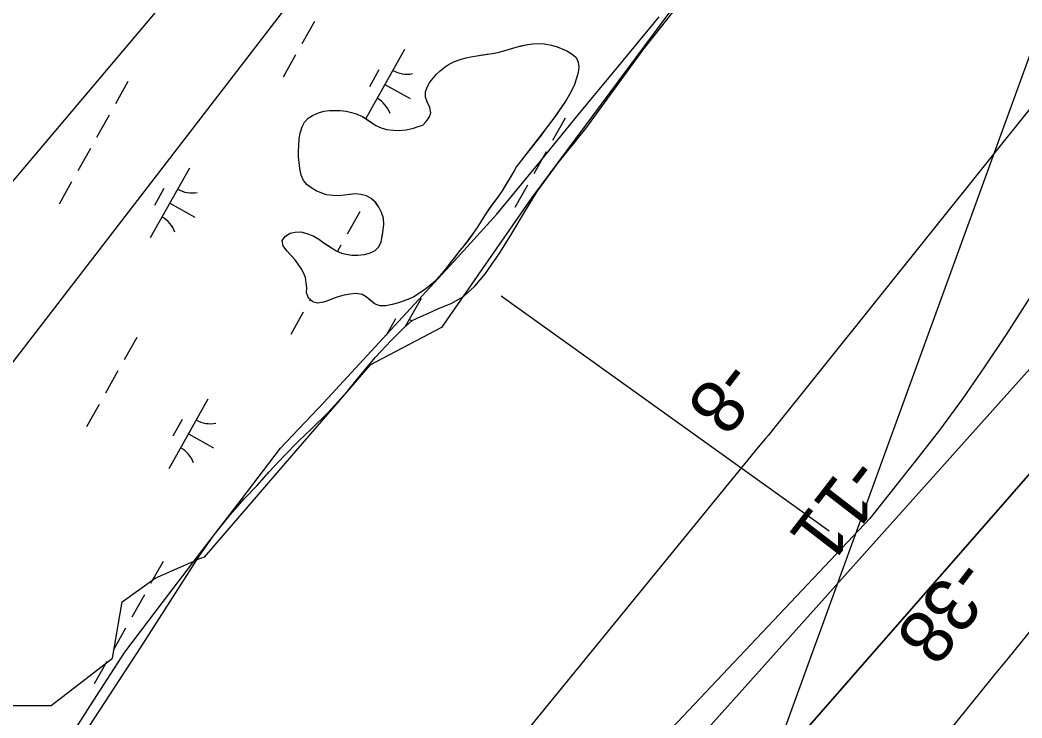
# Model space of a CAD drawing. Extents: x 3913936 to 3933962, y 195330 to 217741.
# Drawn here: x 3922323 to 3922950, y 202121 to 202558 of the extents above; entities that cross this region are included whole.
import ezdxf

# ---------------------------------------------------------------- set-up
doc = ezdxf.new("R2010")
doc.units = 0
for name, color, linetype in [('V-ANNO-TEXT', 7, 'Continuous'), ('V-LEVE-TOET', 7, 'Continuous'), ('V-RIVR-EDGE', 7, 'Continuous'), ('V-RIVR-RANG', 7, 'Continuous'), ('V-RRAP-FSHR', 7, 'Continuous'), ('V-TOPO-DPTH', 7, 'Continuous'), ('V-TOPO-MINR', 7, 'Continuous'), ('V-TOPO-SHOR', 7, 'Continuous'), ('V-UTIL-LINE', 7, 'Continuous'), ('V-WETL-SWMP', 7, 'Continuous')]:
    doc.layers.add(name, color=color, linetype=linetype)

msp = doc.modelspace()

# ---------------------------------------------------------------- linework, layer by layer
at = {"layer": 'V-ANNO-TEXT'}
msp.add_lwpolyline([(3923713.15, 204620.63), (3922595.25, 201547.11)], dxfattribs=at)
at = {"layer": 'V-LEVE-TOET'}
msp.add_line((3922624.2, 202385.16), (3922829.43, 202238.05), dxfattribs=at)
at = {"layer": 'V-RIVR-EDGE'}
for points in [[(3923006.45, 202985.36), (3922949.87, 202946.46), (3922920.41, 202907.57), (3922890.94, 202843.92), (3922886.22, 202788.52), (3922866.19, 202747.26), (3922643.41, 202446.69), (3922586.83, 202365.36), (3922542.04, 202341.78), (3922489, 202280.49), (3922438.31, 202221.56), (3922433.64, 202219.89)], [(3922301.36, 202128.83), (3922342.66, 202128.83), (3922381.02, 202158.33), (3922386.92, 202193.73), (3922407.57, 202208.48), (3922433.64, 202219.89)]]:
    msp.add_lwpolyline(points, dxfattribs=at)
at = {"layer": 'V-RRAP-FSHR'}
msp.add_lwpolyline([(3922302.51, 202027.32), (3922324.2, 202061.57), (3922345.5, 202094.79), (3922366.99, 202128.52), (3922388.58, 202162.2), (3922412.85, 202193.98), (3922437.13, 202225.77), (3922461.41, 202257.56), (3922486.14, 202289.78), (3922513.12, 202318.49), (3922540.22, 202347.91), (3922567.33, 202377.33), (3922594.43, 202406.74), (3922621.49, 202436.2), (3922646.86, 202467.13), (3922672.22, 202498.55), (3922697.59, 202528.98), (3922722.95, 202559.91)], dxfattribs=at)
at = {"layer": 'V-TOPO-DPTH'}
for points in [[(3923377.96, 202699), (3922941.35, 202158.48), (3922940.31, 202157.2), (3922937.13, 202153.43), (3922933.95, 202149.66), (3922932.91, 202148.38), (3922620.43, 201761.19), (3922567.77, 201695.94), (3922515.1, 201630.7), (3922462.43, 201565.47), (3922409.75, 201500.24), (3922320.06, 201389.21), (3922312.18, 201379.53), (3922304.23, 201369.9), (3922296.21, 201360.34), (3922288.13, 201350.82), (3922167.81, 201210.31), (3922100.01, 201130.19), (3922032.83, 201049.55), (3921966.59, 200968.13), (3921900.98, 200886.2)], [(3923377.96, 202699), (3922941.35, 202158.48), (3922940.31, 202157.2), (3922937.13, 202153.43), (3922933.95, 202149.66), (3922932.91, 202148.38), (3922620.43, 201761.19), (3922567.77, 201695.94), (3922515.1, 201630.7), (3922462.43, 201565.47), (3922409.75, 201500.24), (3922320.06, 201389.21), (3922312.18, 201379.53), (3922304.23, 201369.9), (3922296.21, 201360.34), (3922288.13, 201350.82), (3922167.81, 201210.31), (3922100.01, 201130.19), (3922032.83, 201049.55), (3921966.59, 200968.13), (3921900.98, 200886.2)], [(3923095.91, 202678.46), (3922791.11, 202297.8), (3922789.59, 202295.95), (3922787.26, 202293.23), (3922784.95, 202290.48), (3922157.44, 201521.67), (3922155.7, 201519.54), (3922153.96, 201517.41), (3922152.21, 201515.29), (3922150.47, 201513.16), (3922148.07, 201510.25), (3922146.97, 201508.92), (3922146.42, 201508.26), (3922145.87, 201507.61), (3922141.95, 201502.95), (3922139.44, 201499.96), (3922136.94, 201496.96), (3922134.44, 201493.96), (3922131.96, 201490.95), (3921528.01, 200758.19)], [(3923045.56, 202377.72), (3922233.85, 201449.62), (3922231.73, 201447.13), (3922229.61, 201444.64), (3922227.46, 201442.17), (3922225.3, 201439.71), (3922161.81, 201367.9), (3922127.91, 201329.54), (3922094.02, 201291.17), (3922060.15, 201252.77), (3922026.29, 201214.37), (3921757.53, 200909.33)], [(3921757.53, 200909.33), (3922026.29, 201214.37), (3922060.15, 201252.77), (3922094.02, 201291.17), (3922127.91, 201329.54), (3922161.81, 201367.9), (3922225.3, 201439.71), (3922227.46, 201442.17), (3922229.61, 201444.64), (3922231.73, 201447.13), (3922233.85, 201449.62), (3923045.56, 202377.72)], [(3921571.56, 200731.02), (3921771, 200981.89), (3921838.64, 201066.04), (3921906.88, 201149.7), (3921976, 201232.63), (3922045.72, 201315.07), (3922153.04, 201440.58), (3922169.51, 201459.92), (3922185.93, 201479.31), (3922202.27, 201498.77), (3922970.95, 202357.51)], [(3921571.56, 200731.02), (3921771, 200981.89), (3921838.64, 201066.04), (3921906.88, 201149.7), (3921976, 201232.63), (3922045.72, 201315.07), (3922153.04, 201440.58), (3922169.51, 201459.92), (3922185.93, 201479.31), (3922202.27, 201498.77), (3922970.95, 202357.51)]]:
    msp.add_lwpolyline(points, dxfattribs=at)
at = {"layer": 'V-TOPO-MINR'}
for points in [[(3923377.96, 202699), (3922941.35, 202158.48), (3922940.31, 202157.2), (3922937.13, 202153.43), (3922933.95, 202149.66), (3922932.91, 202148.38), (3922620.43, 201761.19), (3922567.77, 201695.94), (3922515.1, 201630.7), (3922462.43, 201565.47), (3922409.75, 201500.24), (3922320.06, 201389.21), (3922312.18, 201379.53), (3922304.23, 201369.9), (3922296.21, 201360.34), (3922288.13, 201350.82), (3922167.81, 201210.31), (3922100.01, 201130.19), (3922032.83, 201049.55), (3921966.59, 200968.13), (3921900.98, 200886.2)], [(3923095.91, 202678.46), (3922791.11, 202297.8), (3922789.59, 202295.95), (3922787.26, 202293.23), (3922784.95, 202290.48), (3922157.44, 201521.67), (3922155.7, 201519.54), (3922153.96, 201517.41), (3922152.21, 201515.29), (3922150.47, 201513.16), (3922148.07, 201510.25), (3922146.97, 201508.92), (3922146.42, 201508.26), (3922145.87, 201507.61), (3922141.95, 201502.95), (3922139.44, 201499.96), (3922136.94, 201496.96), (3922134.44, 201493.96), (3922131.96, 201490.95), (3921528.01, 200758.19)], [(3922956.69, 202387.01), (3922940, 202360.98), (3922926.57, 202340.72), (3922912.73, 202320.75), (3922898.3, 202301.2), (3922883.47, 202281.95), (3922854.79, 202245.85), (3922330.9, 201690.94), (3922303.28, 201658.32), (3922275.74, 201625.63), (3922248.33, 201592.82), (3922221.02, 201559.94), (3922183.26, 201514.3), (3922174.87, 201504.2), (3922166.46, 201494.11), (3922158, 201484.06), (3922149.52, 201474.03), (3922091.91, 201406.13), (3922054.74, 201362.05), (3922017.74, 201317.82), (3921981.01, 201273.38), (3921944.45, 201228.79), (3921549.88, 200744.53)], [(3923045.56, 202377.72), (3922233.85, 201449.62), (3922231.73, 201447.13), (3922229.61, 201444.64), (3922227.46, 201442.17), (3922225.3, 201439.71), (3922161.81, 201367.9), (3922127.91, 201329.54), (3922094.02, 201291.17), (3922060.15, 201252.77), (3922026.29, 201214.37), (3921757.53, 200909.33)], [(3922970.95, 202357.51), (3922202.27, 201498.77), (3922185.93, 201479.31), (3922169.51, 201459.92), (3922153.04, 201440.58), (3922045.72, 201315.07), (3921976, 201232.63), (3921906.88, 201149.7), (3921838.64, 201066.04), (3921771, 200981.89), (3921571.56, 200731.02)]]:
    msp.add_lwpolyline(points, dxfattribs=at)
at = {"layer": 'V-TOPO-SHOR'}
for points in [[(3922502.82, 202454.65), (3922500.49, 202457.39), (3922499.1, 202460.75), (3922498.23, 202464.79), (3922497.7, 202468.66), (3922497.43, 202472.27), (3922497.34, 202475.63), (3922497.5, 202479.16), (3922497.83, 202483.38), (3922498.34, 202486.9), (3922499.53, 202490.86), (3922501.16, 202493.97), (3922503.48, 202496.47), (3922506.14, 202498.11), (3922509.75, 202499.76), (3922513.19, 202500.8), (3922516.71, 202501.24), (3922519.73, 202501.16), (3922523.34, 202501.09), (3922527.21, 202500.67), (3922530.4, 202499.99), (3922533.41, 202499.05), (3922537.38, 202497.42), (3922540.22, 202495.54), (3922543.07, 202493.65), (3922545.82, 202491.85), (3922549.01, 202490.23), (3922552.46, 202489.29), (3922556.76, 202488.87), (3922560.38, 202488.71), (3922564.68, 202489.15), (3922569.23, 202490.03), (3922572.25, 202491.15), (3922575.17, 202492.02), (3922577.31, 202494.27), (3922579.03, 202496.77), (3922580.22, 202499.78), (3922579.44, 202503.14), (3922577.88, 202506.57), (3922576.84, 202509.49), (3922576.83, 202512.85), (3922577.94, 202515.87), (3922579.57, 202518.88), (3922581.62, 202521.38), (3922583.77, 202523.88), (3922586, 202526.04), (3922589, 202528.46), (3922591.5, 202530.27), (3922595.02, 202531.83), (3922599.15, 202533.22), (3922602.16, 202534.09), (3922605.16, 202534.79), (3922608.95, 202535.48), (3922612.39, 202536.01), (3922615.4, 202536.36), (3922618.5, 202536.8), (3922622.11, 202537.5), (3922625.89, 202538.54), (3922629.33, 202539.5), (3922633.54, 202540.89), (3922637.5, 202541.85), (3922640.6, 202542.54), (3922643.87, 202542.98), (3922647.22, 202543.16), (3922651.27, 202542.92), (3922655.57, 202542.15), (3922659.19, 202540.96), (3922662.29, 202539.68), (3922665.13, 202538.48), (3922668.58, 202536.34), (3922670.99, 202534.28), (3922672.29, 202531.45), (3922672.73, 202528.35), (3922672.31, 202524.99), (3922671.37, 202521.46), (3922669.92, 202517.5), (3922668.47, 202514.31), (3922666.93, 202511.3), (3922665.22, 202508.36), (3922663.25, 202505.26), (3922660.93, 202501.73), (3922658.96, 202498.88), (3922656.56, 202495.52), (3922653.82, 202491.9), (3922651.33, 202488.62), (3922649.36, 202486.03), (3922636.07, 202468.96)], [(3922636.07, 202468.96), (3922633.75, 202466.03), (3922632.3, 202463.36), (3922630.5, 202460.43), (3922628.79, 202457.49), (3922626.3, 202453.44), (3922624.67, 202450.86), (3922622.79, 202448.1), (3922620.73, 202445.34), (3922618.68, 202442.58), (3922616.7, 202439.82), (3922614.73, 202436.98), (3922613.02, 202434.22), (3922611.13, 202431.37), (3922609.08, 202428.01), (3922606.68, 202424.39), (3922603.85, 202420.51), (3922600.85, 202416.54), (3922598.36, 202413.61), (3922594.93, 202409.12), (3922592.27, 202405.85), (3922589.7, 202402.49), (3922587.21, 202399.38), (3922584.9, 202396.79), (3922582.84, 202394.46), (3922579.06, 202391.18), (3922576.23, 202389.02), (3922573.57, 202387.3), (3922569.53, 202384.62), (3922566.69, 202383.32), (3922562.91, 202381.93), (3922559.81, 202380.89), (3922555.95, 202379.67), (3922551.99, 202378.89), (3922548.38, 202378.96), (3922545.36, 202379.9), (3922542.6, 202382.13), (3922539.75, 202384.53), (3922537.08, 202385.99), (3922533.21, 202386.67), (3922529.68, 202386.31), (3922525.98, 202385.61), (3922522.8, 202384.74), (3922519.71, 202383.7), (3922516.01, 202382.23), (3922512.92, 202381.19), (3922509.31, 202380.66), (3922506.21, 202381.51), (3922503.62, 202383.66), (3922502.32, 202387.27), (3922502.48, 202390.28), (3922502.21, 202393.29), (3922501.77, 202396.56), (3922500.56, 202399.57), (3922499, 202402.23), (3922497.19, 202404.98), (3922494.95, 202407.99), (3922492.18, 202410.99), (3922489.94, 202413.31), (3922487.69, 202416.49), (3922487.17, 202419.75), (3922489.23, 202422.51), (3922492.15, 202424.33), (3922495.33, 202425.11), (3922498.85, 202425.21), (3922502.47, 202424.27), (3922506.95, 202422.48), (3922510.14, 202420.68), (3922512.56, 202418.79), (3922515.23, 202416.99), (3922518.33, 202415.02), (3922521, 202413.4), (3922524.19, 202411.94), (3922527.12, 202411.18), (3922530.65, 202410.67), (3922534.43, 202410.68), (3922538.65, 202410.95), (3922542.43, 202412.08), (3922545.27, 202413.63), (3922547.58, 202415.79), (3922549.04, 202418.98), (3922549.89, 202423.46), (3922550.39, 202426.55), (3922550.73, 202429.83), (3922550.55, 202433.87), (3922549.25, 202437.39), (3922547.52, 202440.66), (3922545.61, 202443.58), (3922542.85, 202446.07), (3922539.92, 202447.7), (3922536.31, 202448.63), (3922533.3, 202448.97), (3922529.25, 202448.53), (3922526.07, 202448.09), (3922522.89, 202447.82), (3922518.75, 202447.89), (3922514.88, 202448.31), (3922511.87, 202449.34), (3922508.42, 202450.96), (3922505.58, 202452.59), (3922502.82, 202454.65)]]:
    msp.add_lwpolyline(points, dxfattribs=at)
at = {"layer": 'V-UTIL-LINE'}
for points in [[(3928315.82, 212388.13), (3926944.7, 210748.94), (3926592.74, 210251.47), (3926408.93, 209914.99), (3925628.64, 208474.44), (3925139.98, 207727.42), (3924555.96, 206253.65), (3924055.82, 204771.45), (3923484.9, 203858.52), (3922256.01, 202262.65), (3921816.4, 201905.57), (3920704.84, 200345.08), (3920462.44, 200062.72)], [(3928328.32, 212380.93), (3926784.14, 210502.92), (3926424.72, 209908.68), (3925640.45, 208467.64), (3924952.2, 207329.25), (3923971.74, 204752.16), (3923252.9, 203563.68), (3921560.17, 201558.84), (3920397.87, 200112.86)]]:
    msp.add_lwpolyline(points, dxfattribs=at)
at = {"layer": 'V-WETL-SWMP'}
for p, q in [((3922712.83, 202538.87), (3922754.11, 202591.47)), ((3922507.32, 202556.9), (3922499.48, 202542.95)), ((3922633.54, 202540.89), (3922640.6, 202542.54)), ((3922640.6, 202542.54), (3922643.87, 202542.98)), ((3922643.87, 202542.98), (3922647.22, 202543.17)), ((3922647.22, 202543.17), (3922651.27, 202542.92)), ((3922651.27, 202542.92), (3922655.57, 202542.15)), ((3922655.57, 202542.15), (3922659.19, 202540.96)), ((3922495.56, 202535.98), (3922487.72, 202522.03)), ((3922563.65, 202539.34), (3922539.36, 202496.12)), ((3922602.16, 202534.09), (3922605.17, 202534.79)), ((3922605.17, 202534.79), (3922608.95, 202535.49)), ((3922608.95, 202535.49), (3922618.5, 202536.8)), ((3922618.5, 202536.8), (3922622.11, 202537.5)), ((3922622.11, 202537.5), (3922629.33, 202539.5)), ((3922629.33, 202539.5), (3922633.54, 202540.89)), ((3922659.19, 202540.96), (3922665.13, 202538.48)), ((3922665.13, 202538.48), (3922668.58, 202536.34)), ((3922668.58, 202536.34), (3922670.99, 202534.28)), ((3922677.21, 202489.88), (3922712.83, 202538.87)), ((3922589, 202528.46), (3922591.5, 202530.27)), ((3922591.5, 202530.27), (3922595.02, 202531.83)), ((3922595.02, 202531.83), (3922599.15, 202533.22)), ((3922599.15, 202533.22), (3922602.16, 202534.09)), ((3922670.99, 202534.28), (3922672.29, 202531.45)), ((3922672.29, 202531.45), (3922672.73, 202528.35)), ((3922547.62, 202526.56), (3922541.74, 202516.09)), ((3922579.57, 202518.88), (3922583.77, 202523.89)), ((3922583.77, 202523.89), (3922586, 202526.04)), ((3922586, 202526.04), (3922589, 202528.46)), ((3922672.31, 202524.99), (3922671.37, 202521.46)), ((3922672.73, 202528.35), (3922672.31, 202524.99)), ((3922390.65, 202519.24), (3922382.81, 202505.29)), ((3922551.4, 202517.54), (3922567.1, 202508.72)), ((3922577.94, 202515.87), (3922579.57, 202518.88)), ((3922669.92, 202517.5), (3922668.47, 202514.31)), ((3922671.37, 202521.46), (3922669.92, 202517.5)), ((3922576.83, 202512.85), (3922577.94, 202515.87)), ((3922576.84, 202509.49), (3922576.83, 202512.85)), ((3922666.93, 202511.3), (3922665.21, 202508.36)), ((3922668.47, 202514.31), (3922666.93, 202511.3)), ((3922577.88, 202506.57), (3922576.84, 202509.49)), ((3922579.44, 202503.14), (3922577.88, 202506.57)), ((3922665.21, 202508.36), (3922660.93, 202501.73)), ((3922378.89, 202498.32), (3922371.04, 202484.37)), ((3922503.48, 202496.47), (3922506.14, 202498.11)), ((3922506.14, 202498.11), (3922509.75, 202499.76)), ((3922509.75, 202499.76), (3922513.19, 202500.8)), ((3922513.19, 202500.8), (3922516.71, 202501.24)), ((3922516.71, 202501.24), (3922523.34, 202501.08)), ((3922523.34, 202501.08), (3922527.21, 202500.67)), ((3922527.21, 202500.67), (3922530.4, 202499.99)), ((3922530.4, 202499.99), (3922533.41, 202499.05)), ((3922533.41, 202499.05), (3922537.38, 202497.42)), ((3922537.38, 202497.42), (3922545.82, 202491.85)), ((3922579.03, 202496.77), (3922580.22, 202499.78)), ((3922580.22, 202499.78), (3922579.44, 202503.14)), ((3922660.93, 202501.73), (3922656.56, 202495.52)), ((3922498.34, 202486.9), (3922499.53, 202490.86)), ((3922499.53, 202490.86), (3922501.16, 202493.97)), ((3922501.16, 202493.97), (3922503.48, 202496.47)), ((3922545.82, 202491.85), (3922549.01, 202490.23)), ((3922569.23, 202490.03), (3922572.24, 202491.15)), ((3922572.24, 202491.15), (3922575.17, 202492.02)), ((3922575.17, 202492.02), (3922577.31, 202494.27)), ((3922577.31, 202494.27), (3922579.03, 202496.77)), ((3922653.82, 202491.9), (3922636.07, 202468.96)), ((3922656.56, 202495.52), (3922653.82, 202491.9)), ((3922664.08, 202496.31), (3922656.24, 202482.37)), ((3922497.83, 202483.37), (3922498.34, 202486.9)), ((3922549.01, 202490.23), (3922552.46, 202489.29)), ((3922552.46, 202489.29), (3922556.76, 202488.87)), ((3922556.76, 202488.87), (3922560.38, 202488.71)), ((3922560.38, 202488.71), (3922564.68, 202489.15)), ((3922564.68, 202489.15), (3922569.23, 202490.03)), ((3922659.77, 202468.48), (3922677.21, 202489.88)), ((3922497.34, 202475.63), (3922497.5, 202479.16)), ((3922497.5, 202479.16), (3922497.83, 202483.37)), ((3922367.12, 202477.4), (3922359.28, 202463.45)), ((3922497.43, 202472.27), (3922497.34, 202475.63)), ((3922497.7, 202468.66), (3922497.43, 202472.27)), ((3922652.32, 202475.39), (3922644.48, 202461.44)), ((3922498.23, 202464.79), (3922497.7, 202468.66)), ((3922633.75, 202466.03), (3922632.3, 202463.36)), ((3922636.07, 202468.96), (3922633.75, 202466.03)), ((3922646.7, 202450.43), (3922659.77, 202468.48)), ((3922429.05, 202465.05), (3922404.55, 202421.46)), ((3922499.1, 202460.75), (3922498.23, 202464.79)), ((3922500.49, 202457.39), (3922499.1, 202460.75)), ((3922632.3, 202463.36), (3922624.67, 202450.86)), ((3922355.36, 202456.48), (3922347.52, 202442.53)), ((3922502.82, 202454.65), (3922500.49, 202457.39)), ((3922505.58, 202452.59), (3922502.82, 202454.65)), ((3922640.56, 202454.47), (3922632.72, 202440.52)), ((3922413.02, 202452.27), (3922407.14, 202441.8)), ((3922508.42, 202450.96), (3922505.58, 202452.59)), ((3922511.87, 202449.34), (3922508.42, 202450.96)), ((3922514.88, 202448.31), (3922511.87, 202449.34)), ((3922518.75, 202447.89), (3922514.88, 202448.31)), ((3922522.89, 202447.82), (3922518.75, 202447.89)), ((3922526.07, 202448.09), (3922522.89, 202447.82)), ((3922533.29, 202448.97), (3922526.07, 202448.09)), ((3922536.31, 202448.63), (3922533.29, 202448.97)), ((3922539.92, 202447.69), (3922536.31, 202448.63)), ((3922542.85, 202446.07), (3922539.92, 202447.69)), ((3922622.79, 202448.1), (3922618.67, 202442.58)), ((3922624.67, 202450.86), (3922622.79, 202448.1)), ((3922638.5, 202437.03), (3922646.7, 202450.43)), ((3922416.8, 202443.25), (3922432.49, 202434.43)), ((3922545.62, 202443.58), (3922542.85, 202446.07)), ((3922547.52, 202440.66), (3922545.62, 202443.58)), ((3922618.67, 202442.58), (3922614.73, 202436.98)), ((3922535.64, 202437.73), (3922527.8, 202423.78)), ((3922549.25, 202437.39), (3922547.52, 202440.66)), ((3922550.55, 202433.87), (3922549.25, 202437.39)), ((3922614.73, 202436.98), (3922609.08, 202428.01)), ((3922630.82, 202424.14), (3922638.5, 202437.03)), ((3922550.4, 202426.55), (3922550.73, 202429.83)), ((3922550.73, 202429.83), (3922550.55, 202433.87)), ((3922487.17, 202419.75), (3922489.23, 202422.51)), ((3922489.23, 202422.51), (3922492.15, 202424.33)), ((3922492.15, 202424.33), (3922495.33, 202425.11)), ((3922495.33, 202425.11), (3922498.85, 202425.21)), ((3922498.85, 202425.21), (3922502.47, 202424.27)), ((3922502.47, 202424.27), (3922506.95, 202422.48)), ((3922506.95, 202422.48), (3922510.14, 202420.68)), ((3922549.04, 202418.98), (3922550.4, 202426.55)), ((3922606.68, 202424.39), (3922600.85, 202416.54)), ((3922609.08, 202428.01), (3922606.68, 202424.39)), ((3922623.39, 202412.03), (3922630.82, 202424.14)), ((3922487.69, 202416.49), (3922487.17, 202419.75)), ((3922489.94, 202413.31), (3922487.69, 202416.49)), ((3922510.14, 202420.68), (3922512.56, 202418.79)), ((3922512.56, 202418.79), (3922518.33, 202415.02)), ((3922523.88, 202416.81), (3922521.77, 202413.05)), ((3922545.27, 202413.63), (3922547.58, 202415.79)), ((3922547.58, 202415.79), (3922549.04, 202418.98)), ((3922600.85, 202416.54), (3922598.36, 202413.61)), ((3922494.95, 202407.99), (3922489.94, 202413.31)), ((3922518.33, 202415.02), (3922521, 202413.39)), ((3922521, 202413.39), (3922524.19, 202411.94)), ((3922524.19, 202411.94), (3922527.12, 202411.17)), ((3922527.12, 202411.17), (3922530.65, 202410.67)), ((3922530.65, 202410.67), (3922534.43, 202410.68)), ((3922534.43, 202410.68), (3922538.65, 202410.95)), ((3922538.65, 202410.95), (3922542.43, 202412.08)), ((3922542.43, 202412.08), (3922545.27, 202413.63)), ((3922598.36, 202413.61), (3922589.7, 202402.49)), ((3922614.42, 202399.14), (3922623.39, 202412.03)), ((3922497.19, 202404.98), (3922494.95, 202407.99)), ((3922499, 202402.23), (3922497.19, 202404.98)), ((3922500.56, 202399.57), (3922499, 202402.23)), ((3922501.77, 202396.56), (3922500.56, 202399.57)), ((3922587.21, 202399.38), (3922582.84, 202394.46)), ((3922589.7, 202402.49), (3922587.21, 202399.38)), ((3922607.75, 202391.14), (3922614.42, 202399.14)), ((3922502.21, 202393.29), (3922501.77, 202396.56)), ((3922502.48, 202390.28), (3922502.21, 202393.29)), ((3922579.06, 202391.18), (3922576.23, 202389.02)), ((3922582.84, 202394.46), (3922579.06, 202391.18)), ((3922600.57, 202384.69), (3922607.75, 202391.14)), ((3922502.32, 202387.27), (3922502.48, 202390.28)), ((3922503.62, 202383.66), (3922502.32, 202387.27)), ((3922522.8, 202384.74), (3922519.71, 202383.7)), ((3922525.98, 202385.61), (3922522.8, 202384.74)), ((3922529.68, 202386.31), (3922525.98, 202385.61)), ((3922533.21, 202386.67), (3922529.68, 202386.31)), ((3922537.08, 202385.99), (3922533.21, 202386.67)), ((3922539.76, 202384.53), (3922537.08, 202385.99)), ((3922545.36, 202379.9), (3922539.76, 202384.53)), ((3922569.53, 202384.62), (3922566.69, 202383.32)), ((3922576.23, 202389.02), (3922569.53, 202384.62)), ((3922592.86, 202380.3), (3922600.57, 202384.69)), ((3922506.21, 202381.51), (3922503.62, 202383.66)), ((3922504.73, 202382.74), (3922504.28, 202381.94)), ((3922509.31, 202380.66), (3922506.21, 202381.51)), ((3922512.92, 202381.19), (3922509.31, 202380.66)), ((3922516.01, 202382.23), (3922512.92, 202381.19)), ((3922519.71, 202383.7), (3922516.01, 202382.23)), ((3922548.38, 202378.96), (3922545.36, 202379.9)), ((3922551.99, 202378.89), (3922548.38, 202378.96)), ((3922555.95, 202379.67), (3922551.99, 202378.89)), ((3922559.82, 202380.89), (3922555.95, 202379.67)), ((3922566.69, 202383.32), (3922559.82, 202380.89)), ((3922574.05, 202383.54), (3922564.17, 202365.97)), ((3922584.89, 202377.18), (3922592.86, 202380.3)), ((3922500.36, 202374.97), (3922492.52, 202361.02)), ((3922568.45, 202369.68), (3922573.84, 202372.27)), ((3922573.84, 202372.27), (3922578.73, 202374.34)), ((3922578.73, 202374.34), (3922584.89, 202377.18)), ((3922558.01, 202370.76), (3922552.13, 202360.3)), ((3922562.8, 202364.77), (3922568.45, 202369.68)), ((3922555.36, 202357.29), (3922562.8, 202364.77)), ((3922396.11, 202359.06), (3922388.26, 202345.12)), ((3922545.61, 202346.71), (3922555.36, 202357.29)), ((3922534.07, 202333.05), (3922545.61, 202346.71)), ((3922384.34, 202338.14), (3922376.5, 202324.19)), ((3922527.92, 202325.57), (3922534.07, 202333.05)), ((3922515.6, 202311.9), (3922527.92, 202325.57)), ((3922372.58, 202317.22), (3922364.74, 202303.27)), ((3922440.68, 202320.58), (3922416.18, 202276.99)), ((3922505.34, 202301.83), (3922515.6, 202311.9)), ((3922424.65, 202307.8), (3922418.77, 202297.34)), ((3922428.43, 202298.79), (3922444.12, 202289.96)), ((3922497.64, 202294.35), (3922505.34, 202301.83)), ((3922488.15, 202284.8), (3922497.64, 202294.35)), ((3922478.91, 202275), (3922488.15, 202284.8)), ((3922471.48, 202266.49), (3922478.91, 202275)), ((3922463.52, 202258.23), (3922471.48, 202266.49)), ((3922454.54, 202248.17), (3922463.52, 202258.23)), ((3922444.55, 202235.54), (3922454.54, 202248.17)), ((3922435.58, 202222.9), (3922444.55, 202235.54)), ((3922398.43, 202164.91), (3922435.58, 202222.9)), ((3922412.67, 202218.97), (3922404.83, 202205.03)), ((3922400.91, 202198.05), (3922393.07, 202184.1)), ((3922389.15, 202177.13), (3922381.31, 202163.18)), ((3922363.33, 202110.78), (3922398.43, 202164.91)), ((3922377.39, 202156.21), (3922369.55, 202142.26))]:
    msp.add_line(p, q, dxfattribs=at)
for centre, start, end in [((3922565.15, 202541.51), 239.88608, 281.42974), ((3922538.08, 202493.35), 19.88608, 61.42973), ((3922430.54, 202467.22), 239.88608, 281.42974), ((3922403.47, 202419.06), 19.88608, 61.42973), ((3922575.54, 202385.71), 239.88608, 245.97899), ((3922442.17, 202322.75), 239.88608, 281.42974), ((3922415.1, 202274.59), 19.88608, 61.42973)]:
    msp.add_arc(centre, 17.62, start, end, dxfattribs=at)

# ---------------------------------------------------------------- texts
at = {"layer": 'V-RIVR-RANG'}
for s, rotation, p in [('-8', 232.29833, (3922763.4, 202347.58)), ('-11', 232.29833, (3922842.91, 202286.94)), ('-38', 232.43814, (3922909.24, 202223.35))]:
    msp.add_text(s, height=33.5, rotation=rotation, dxfattribs=at).set_placement(p)

doc.saveas('drawing.dxf')
